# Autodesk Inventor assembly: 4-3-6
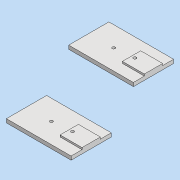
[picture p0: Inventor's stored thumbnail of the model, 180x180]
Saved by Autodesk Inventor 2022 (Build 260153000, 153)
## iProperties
Created: 2021-07
Part Number: 4-3-6
Document SubType Name: Assembly
Designer: DesignLab
Author: DesignLab
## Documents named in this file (2)
- d:\Users\DesignLab\Desktop\ver2022\ch04\4-3-6.iam
- d:\Users\DesignLab\Desktop\ver2022\ch04\03-ベース板_完成.ipt
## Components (2 placed, 1 different names)
1. 03-ベース板_完成:1
2. 03-ベース板_完成:2
